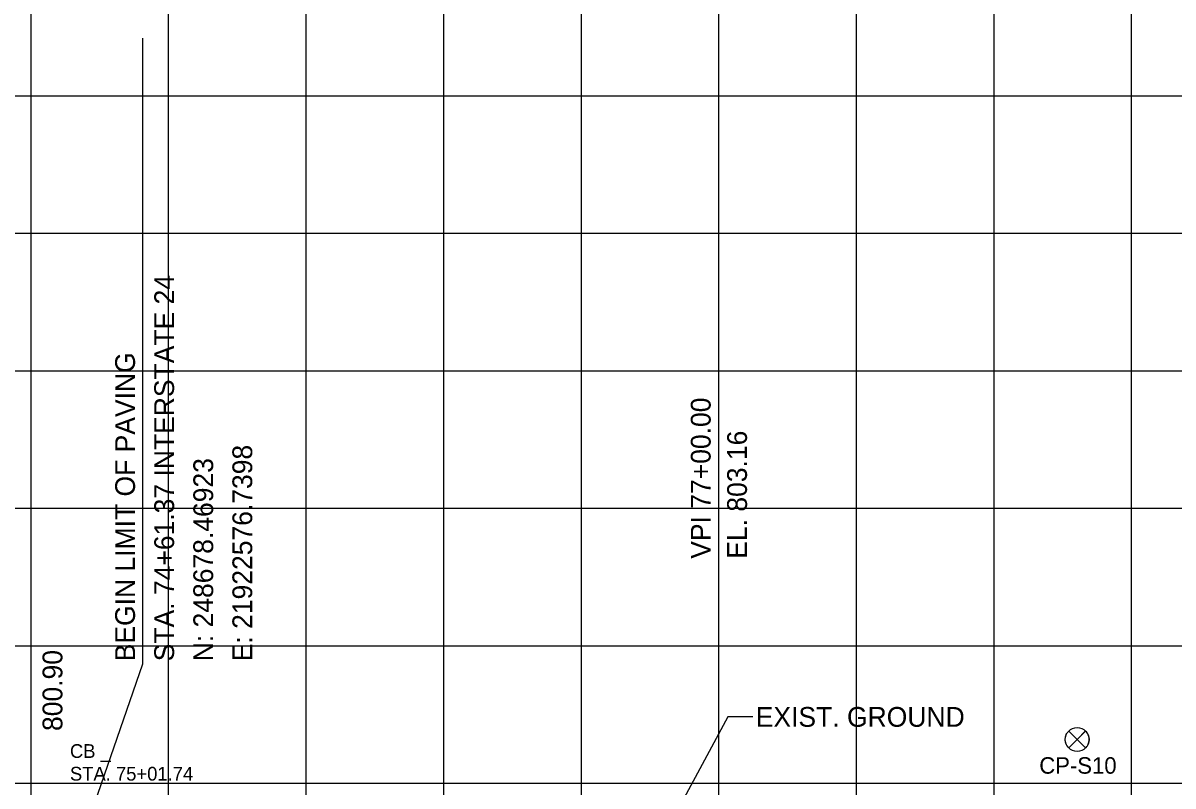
# Model space of a CAD drawing. Extents: x -7164 to 2214450, y -19642 to 253469.
# Drawn here: x 1447.1 to 1865.1, y -1451 to -1173.6 of the extents above; entities that cross this region are included whole.
import ezdxf

# ---------------------------------------------------------------- set-up
doc = ezdxf.new("R2010")
doc.units = 0
for name, color, linetype in [('DESIGN - PROFILE - Proposed Curve Text', 7, 'Continuous'), ('DESIGN - PROFILE - Proposed Text', 7, 'Continuous'), ('DESIGN - SHEET - Light Grid', 7, 'Continuous'), ('SURVEY - PROFILE - Control with Text', 7, 'Continuous'), ('SURVEY - PROFILE - Drainage - Storm Sewer Text', 7, 'Continuous')]:
    doc.layers.add(name, color=color, linetype=linetype)

msp = doc.modelspace()

# ---------------------------------------------------------------- linework, layer by layer
at = {"layer": 'DESIGN - PROFILE - Proposed Text'}
msp.add_line((1490.54, -1179.04), (1490.54, -1406.66), dxfattribs=at)
msp.add_line((1490.54, -1179.04), (1490.54, -1406.66), dxfattribs=at)
for points in [[(1490.54, -1406.66), (1461.37, -1491.01)], [(1490.54, -1406.66), (1461.37, -1491.01)], [(1712.38, -1425.88), (1703.2, -1425.88), (1678.83, -1471.33)], [(1712.38, -1425.88), (1703.2, -1425.88), (1678.83, -1471.33)]]:
    msp.add_lwpolyline(points, dxfattribs=at)
at = {"layer": 'DESIGN - SHEET - Light Grid'}
for p, q in [((1450, -3000), (1450, -1000)), ((1450, -3000), (1450, -1000)), ((1500, -3000), (1500, -1000)), ((1500, -3000), (1500, -1000)), ((1550, -3000), (1550, -1000)), ((1550, -3000), (1550, -1000)), ((1600, -3000), (1600, -1000)), ((1600, -3000), (1600, -1000)), ((1650, -3000), (1650, -1000)), ((1650, -3000), (1650, -1000)), ((1700, -3000), (1700, -1000)), ((1700, -3000), (1700, -1000)), ((1750, -3000), (1750, -1000)), ((1750, -3000), (1750, -1000)), ((1800, -3000), (1800, -1000)), ((1800, -3000), (1800, -1000)), ((1850, -3000), (1850, -1000)), ((1850, -3000), (1850, -1000)), ((0, -1200), (12400, -1200)), ((0, -1200), (12400, -1200)), ((0, -1250), (12400, -1250)), ((0, -1250), (12400, -1250)), ((0, -1300), (12400, -1300)), ((0, -1300), (12400, -1300)), ((0, -1350), (12400, -1350)), ((0, -1350), (12400, -1350)), ((0, -1400), (12400, -1400)), ((0, -1400), (12400, -1400)), ((0, -1450), (12400, -1450)), ((0, -1450), (12400, -1450))]:
    msp.add_line(p, q, dxfattribs=at)
at = {"layer": 'SURVEY - PROFILE - Control with Text'}
for p, q in [((1827.14, -1431.02), (1830.22, -1434.1)), ((1827.14, -1431.02), (1830.22, -1434.1)), ((1830.22, -1434.1), (1833.3, -1431.01)), ((1830.22, -1434.1), (1833.3, -1431.01)), ((1827.15, -1437.16), (1830.22, -1434.1)), ((1827.15, -1437.16), (1830.22, -1434.1)), ((1830.22, -1434.1), (1833.29, -1437.17)), ((1830.22, -1434.1), (1833.29, -1437.17))]:
    msp.add_line(p, q, dxfattribs=at)
for points in [[(1827.15, -1431.03), (1830.22, -1434.1), (1827.16, -1437.15), (1826.91, -1436.9), (1826.66, -1436.57), (1826.5, -1436.33), (1826.33, -1436.01), (1826.18, -1435.68), (1826.08, -1435.4), (1826.01, -1435.14), (1825.94, -1434.85), (1825.9, -1434.56), (1825.88, -1434.3), (1825.88, -1433.97), (1825.89, -1433.7), (1825.92, -1433.46), (1825.96, -1433.26), (1826.01, -1433.03), (1826.09, -1432.76), (1826.16, -1432.55), (1826.25, -1432.32), (1826.43, -1431.97), (1826.62, -1431.64), (1826.91, -1431.28)], [(1827.15, -1431.03), (1830.22, -1434.1), (1827.16, -1437.15), (1826.91, -1436.9), (1826.66, -1436.57), (1826.5, -1436.33), (1826.33, -1436.01), (1826.18, -1435.68), (1826.08, -1435.4), (1826.01, -1435.14), (1825.94, -1434.85), (1825.9, -1434.56), (1825.88, -1434.3), (1825.88, -1433.97), (1825.89, -1433.7), (1825.92, -1433.46), (1825.96, -1433.26), (1826.01, -1433.03), (1826.09, -1432.76), (1826.16, -1432.55), (1826.25, -1432.32), (1826.43, -1431.97), (1826.62, -1431.64), (1826.91, -1431.28)], [(1833.29, -1431.03), (1830.22, -1434.1), (1833.28, -1437.17), (1833.48, -1436.97), (1833.71, -1436.7), (1833.93, -1436.36), (1834.08, -1436.11), (1834.26, -1435.71), (1834.36, -1435.42), (1834.45, -1435.13), (1834.5, -1434.9), (1834.55, -1434.57), (1834.57, -1434.32), (1834.57, -1434.01), (1834.56, -1433.71), (1834.53, -1433.49), (1834.49, -1433.22), (1834.44, -1433.02), (1834.37, -1432.77), (1834.24, -1432.41), (1834.14, -1432.2), (1834.03, -1431.99), (1833.82, -1431.64), (1833.57, -1431.31)], [(1833.29, -1431.03), (1830.22, -1434.1), (1833.28, -1437.17), (1833.48, -1436.97), (1833.71, -1436.7), (1833.93, -1436.36), (1834.08, -1436.11), (1834.26, -1435.71), (1834.36, -1435.42), (1834.45, -1435.13), (1834.5, -1434.9), (1834.55, -1434.57), (1834.57, -1434.32), (1834.57, -1434.01), (1834.56, -1433.71), (1834.53, -1433.49), (1834.49, -1433.22), (1834.44, -1433.02), (1834.37, -1432.77), (1834.24, -1432.41), (1834.14, -1432.2), (1834.03, -1431.99), (1833.82, -1431.64), (1833.57, -1431.31)]]:
    msp.add_lwpolyline(points, close=True, dxfattribs=at)
msp.add_circle((1830.23, -1434.09), 4.35, dxfattribs=at)
msp.add_circle((1830.23, -1434.09), 4.35, dxfattribs=at)

# ---------------------------------------------------------------- texts
at = {"layer": 'DESIGN - PROFILE - Proposed Curve Text'}
for s, p in [('VPI 77+00.00', (1697, -1368.38)), ('VPI 77+00.00', (1697, -1368.38)), ('EL. 803.16', (1710.2, -1368.38)), ('EL. 803.16', (1710.2, -1368.38)), ('800.90', (1461.37, -1431.01)), ('800.90', (1461.37, -1431.01))]:
    msp.add_text(s, height=7.2, rotation=90, dxfattribs=at).set_placement(p)
at = {"layer": 'DESIGN - PROFILE - Proposed Text'}
for s, p in [('STA. 74+61.37 INTERSTATE 24', (1501.97, -1405.66)), ('STA. 74+61.37 INTERSTATE 24', (1501.97, -1405.66)), ('BEGIN LIMIT OF PAVING', (1487.77, -1405.66)), ('BEGIN LIMIT OF PAVING', (1487.77, -1405.66)), ('E: 21922576.7398', (1530.37, -1405.66)), ('E: 21922576.7398', (1530.37, -1405.66)), ('N: 248678.46923', (1516.17, -1405.66)), ('N: 248678.46923', (1516.17, -1405.66))]:
    msp.add_text(s, height=7.2, rotation=90, dxfattribs=at).set_placement(p)
msp.add_text('EXIST. GROUND', height=7.2, dxfattribs=at).set_placement((1713.38, -1429.48))
msp.add_text('EXIST. GROUND', height=7.2, dxfattribs=at).set_placement((1713.38, -1429.48))
at = {"layer": 'SURVEY - PROFILE - Control with Text'}
msp.add_text('CP-S10', height=6, dxfattribs=at).set_placement((1816.45, -1446.54))
msp.add_text('CP-S10', height=6, dxfattribs=at).set_placement((1816.45, -1446.54))
at = {"layer": 'SURVEY - PROFILE - Drainage - Storm Sewer Text'}
for s, p in [('CB _', (1464.12, -1440.8)), ('CB _', (1464.12, -1440.8)), ('STA. 75+01.74', (1464.12, -1449.05)), ('STA. 75+01.74', (1464.12, -1449.05))]:
    msp.add_text(s, height=5, dxfattribs=at).set_placement(p)

doc.saveas('drawing.dxf')
